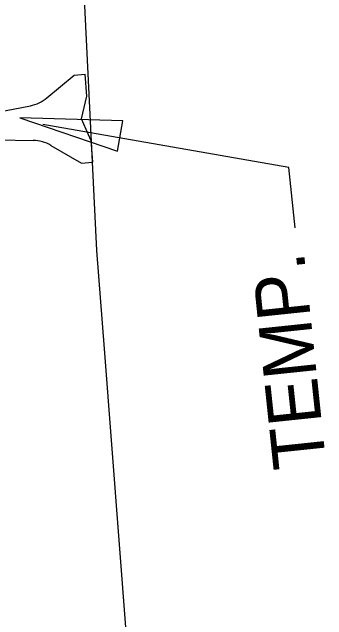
# Model space of a CAD drawing. Extents: x 633427 to 634998, y 288285 to 294065.
# Drawn here: x 634790.7 to 634826.4, y 291207.3 to 291276.2 of the extents above; entities that cross this region are included whole.
import ezdxf

# ---------------------------------------------------------------- set-up
doc = ezdxf.new("R2010")
doc.units = 0
for name, color, linetype in [('Level 58', 7, 'Continuous'), ('R_50 Horz Alg Ticks', 7, 'Continuous'), ('R_Xsect Slope', 7, 'Continuous')]:
    doc.layers.add(name, color=color, linetype=linetype)

# ---------------------------------------------------------------- blocks, each defined once
blk = doc.blocks.new('BARRIER WALL X-SECTION')
at = {"layer": 'R_Xsect Slope'}
for p, q in [((0.795, 2.589), (0.866, 2.65)), ((0.866, 2.65), (1.241, 2.642)), ((1.241, 2.642), (1.308, 2.579)), ((0.795, 2.589), (0.632, 1.285)), ((1.308, 2.579), (1.42, 1.269)), ((0.478, 0.898), (0.005, 0.25)), ((1.558, 0.876), (2.005, 0.21)), ((0.005, 0.25), (0, 0)), ((0.5, -0.01), (1.003, 0.147)), ((1.003, 0.147), (1.5, -0.03)), ((2.005, 0.21), (2, -0.04)), ((0.5, -0.01), (0, 0)), ((1.5, -0.03), (2, -0.04))]:
    blk.add_line(p, q, dxfattribs=at)
for centre, start, end in [((-0.195, 1.389), 323.8622, 352.8452), ((2.25, 1.34), 184.8632, 213.8462)]:
    blk.add_arc(centre, 0.833, start, end, dxfattribs=at)

msp = doc.modelspace()

# ---------------------------------------------------------------- linework, layer by layer
at = {"layer": 'Level 58'}
msp.add_lwpolyline([(634843.21, 291006.347), (634839.848, 291044.589), (634837.594, 291049.718), (634822.881, 291083.243), (634820.152, 291091.08), (634817.269, 291099.36), (634816.367, 291102.205), (634815.732, 291106.694), (634811.007, 291137.245), (634809.865, 291147.267), (634804.505, 291194.623), (634801.169, 291238.02), (634800.295, 291249.138), (634798.887, 291278.474), (634798.515, 291286.462), (634806.906, 291348.618), (634807.995, 291357.507), (634801.947, 291390.091), (634782.441, 291491.601), (634767.684, 291619.226)], dxfattribs=at)
at = {"layer": 'R_50 Horz Alg Ticks'}
for p, q in [((634822.069, 291258.534), (634794.19, 291263.442)), ((634822.786, 291251.713), (634822.069, 291258.534))]:
    msp.add_line(p, q, dxfattribs=at)
msp.add_lwpolyline([(634803.271, 291263.855), (634791.565, 291264.184), (634802.648, 291260.402)], close=True, dxfattribs=at)

# ---------------------------------------------------------------- block references
at = {"xscale": 5, "yscale": 4.999999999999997, "rotation": 96.00000000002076}
msp.add_blockref('BARRIER WALL X-SECTION', (634799.826, 291259.152), dxfattribs=at)

# ---------------------------------------------------------------- texts
at = {"layer": 'R_50 Horz Alg Ticks'}
msp.add_text('TEMP.', height=6, rotation=96, dxfattribs=at).set_placement((634826.336, 291224.737))

doc.saveas('drawing.dxf')
